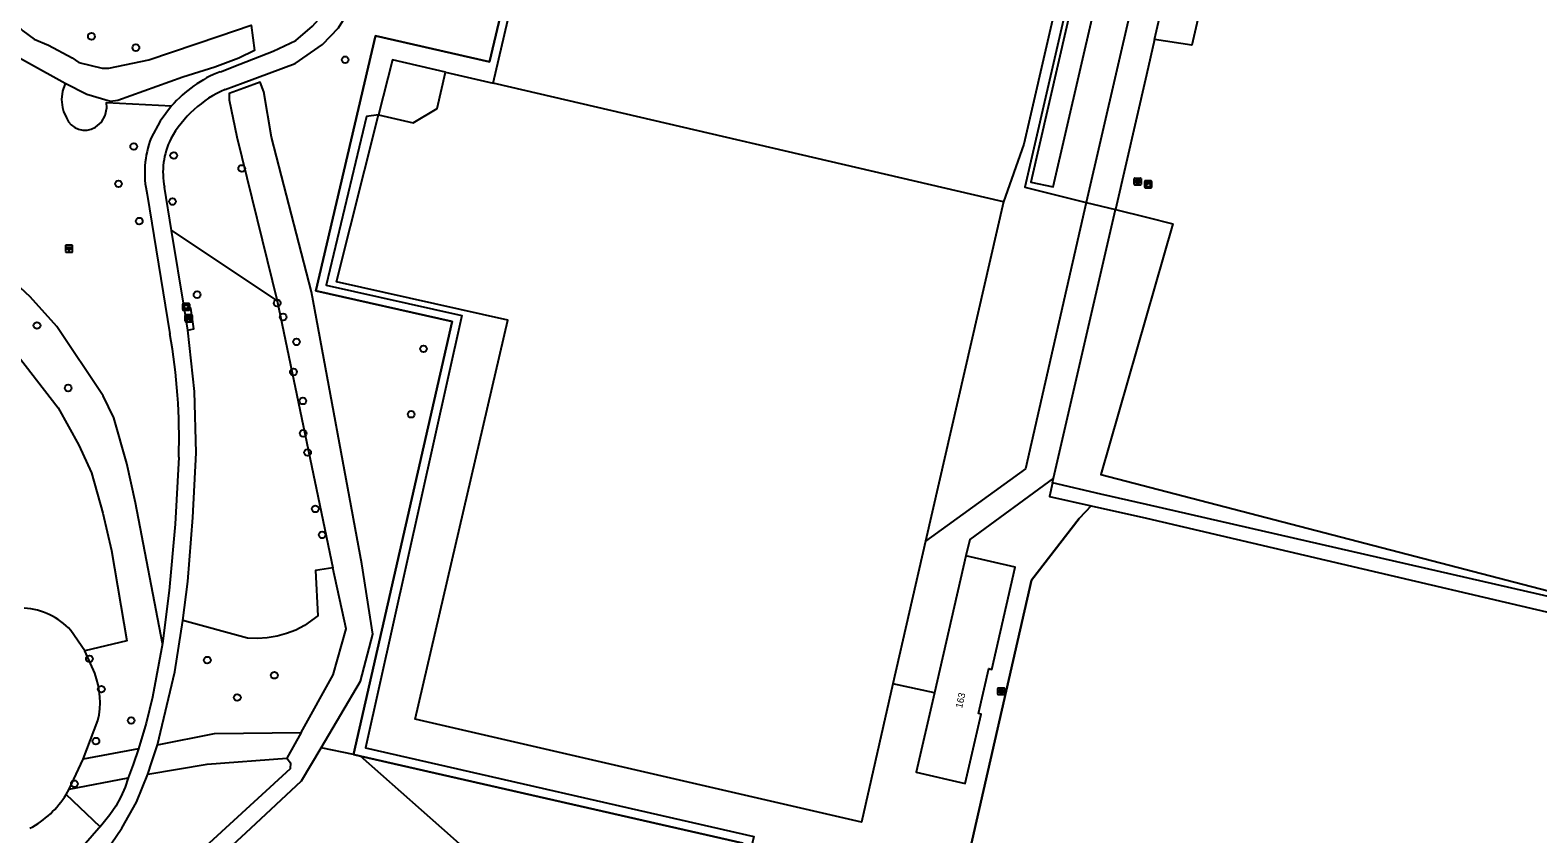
# Model space of a CAD drawing. Extents: x 160203 to 161526, y 379529 to 381797.
# Drawn here: x 160838.5 to 161056.6, y 381499.2 to 381615.5 of the extents above; entities that cross this region are included whole.
import ezdxf

# ---------------------------------------------------------------- set-up
doc = ezdxf.new("R2010")
doc.units = 0
for name, color, linetype in [('IMGEO_Afvalbak', 7, 'Continuous'), ('IMGEO_Bank', 7, 'Continuous'), ('IMGEO_Boom', 7, 'Continuous'), ('IMGEO_Erf', 7, 'Continuous'), ('IMGEO_Fietspad_gesloten', 7, 'Continuous'), ('IMGEO_Gemengd_bos', 7, 'Continuous'), ('IMGEO_Grasland_agrarisch', 7, 'Continuous'), ('IMGEO_Grasland_overig', 7, 'Continuous'), ('IMGEO_Groenvoorziening', 7, 'Continuous'), ('IMGEO_Hectometerpaal', 7, 'Continuous'), ('IMGEO_Hek', 7, 'Continuous'), ('IMGEO_Kast', 7, 'Continuous'), ('IMGEO_Loofbos', 7, 'Continuous'), ('IMGEO_Meer_plas_ven_vijver', 7, 'Continuous'), ('IMGEO_Pand', 7, 'Continuous'), ('IMGEO_Pand_nummerreeks', 7, 'Continuous'), ('IMGEO_Rijbaan_lokaal_gesloten', 7, 'Continuous'), ('IMGEO_Rioolput', 7, 'Continuous'), ('IMGEO_Voetpad_gesloten', 7, 'Continuous'), ('IMGEO_Voetpad_open', 7, 'Continuous'), ('IMGEO_Waterloop', 7, 'Continuous')]:
    doc.layers.add(name, color=color, linetype=linetype)

msp = doc.modelspace()

# ---------------------------------------------------------------- linework, layer by layer
at = {"layer": 'IMGEO_Afvalbak'}
for p, q in [((160860.57, 381575.04), (160860.57, 381575.84)), ((160860.57, 381575.84), (160860.57, 381575.04)), ((160860.67, 381575.94), (160861.45, 381575.94)), ((160861.45, 381575.94), (160860.67, 381575.94)), ((160861.45, 381574.94), (160860.67, 381574.94)), ((160860.67, 381574.94), (160861.45, 381574.94)), ((160861.55, 381575.84), (160861.55, 381575.04)), ((160861.55, 381575.04), (160861.55, 381575.84))]:
    msp.add_line(p, q, dxfattribs=at)
msp.add_lwpolyline([(160860.71, 381575.66), (160861.41, 381575.66), (160861.26, 381575.19), (160860.86, 381575.19), (160860.71, 381575.66)], dxfattribs=at)
for centre, start, end in [((160860.67, 381575.84), 90, 180), ((160860.67, 381575.84), 90, 180), ((160860.67, 381575.04), 180, 270), ((160860.67, 381575.04), 180, 270), ((160861.45, 381575.84), 0, 90), ((160861.45, 381575.84), 360, 90), ((160861.45, 381575.04), 270, 0), ((160861.45, 381575.04), 270, 0)]:
    msp.add_arc(centre, 0.1, start, end, dxfattribs=at)
at = {"layer": 'IMGEO_Bank'}
for p, q in [((160860.92, 381573.34), (160860.92, 381574.18)), ((160860.92, 381574.18), (160860.92, 381573.34)), ((160861, 381574.26), (160861.84, 381574.26)), ((160861.84, 381574.26), (160861, 381574.26)), ((160861.92, 381574.19), (160861.92, 381573.35)), ((160861.92, 381573.35), (160861.92, 381574.19)), ((160861.85, 381573.26), (160861.01, 381573.26)), ((160861.01, 381573.26), (160861.85, 381573.26)), ((160861.23, 381573.77), (160861.23, 381573.87)), ((160861.62, 381573.66), (160861.23, 381573.66)), ((160861.56, 381573.88), (160861.28, 381573.88)), ((160861.28, 381573.87), (160861.28, 381573.77)), ((160861.28, 381573.76), (160861.56, 381573.76)), ((160861.57, 381573.77), (160861.57, 381573.87)), ((160861.61, 381573.87), (160861.61, 381573.77))]:
    msp.add_line(p, q, dxfattribs=at)
for points in [[(160861.17, 381573.66), (160861.03, 381573.66), (160861.14, 381573.76), (160861.23, 381573.76)], [(160861.23, 381573.88), (160861.14, 381573.88), (160861.14, 381574.04), (160861.7, 381574.04), (160861.7, 381573.88), (160861.62, 381573.88)], [(160861.22, 381573.65), (160861.22, 381573.45), (160861.18, 381573.45), (160861.18, 381573.65)], [(160861.62, 381573.76), (160861.7, 381573.76), (160861.82, 381573.66), (160861.68, 381573.66)], [(160861.67, 381573.65), (160861.67, 381573.45), (160861.63, 381573.45), (160861.63, 381573.65)]]:
    msp.add_lwpolyline(points, dxfattribs=at)
for centre, radius, start, end in [((160861, 381574.18), 0.0779, 92.4484, 184.2845), ((160861, 381574.18), 0.0779, 92.4484, 184.2845), ((160861.85, 381574.18), 0.0779, 2.4484, 94.2845), ((160861.85, 381574.18), 0.0779, 2.4484, 94.2845), ((160861, 381573.34), 0.0779, 182.4484, 274.2845), ((160861, 381573.34), 0.0779, 182.4484, 274.2845), ((160861.17, 381573.65), 0.00671, 2.8957, 87.1043), ((160861.23, 381573.65), 0.00671, 92.8957, 177.1043), ((160861.23, 381573.87), 0.00671, 2.8957, 87.1043), ((160861.23, 381573.77), 0.00671, 272.8957, 357.1043), ((160861.28, 381573.87), 0.00671, 92.8957, 177.1043), ((160861.28, 381573.77), 0.00671, 182.8957, 267.1043), ((160861.56, 381573.87), 0.00671, 2.8957, 87.1043), ((160861.56, 381573.77), 0.00671, 272.8957, 357.1043), ((160861.62, 381573.87), 0.00671, 92.8957, 177.1043), ((160861.62, 381573.77), 0.00671, 182.8957, 267.1043), ((160861.62, 381573.65), 0.00671, 2.8957, 87.1043), ((160861.68, 381573.65), 0.00671, 92.8957, 177.1043), ((160861.85, 381573.34), 0.0779, 272.4484, 4.2845), ((160861.85, 381573.34), 0.0779, 272.4484, 4.2845)]:
    msp.add_arc(centre, radius, start, end, dxfattribs=at)
at = {"layer": 'IMGEO_Boom'}
for centre in [(160847.35, 381614.57), (160853.79, 381612.93), (160884.06, 381611.18), (160853.48, 381598.63), (160859.26, 381597.33), (160869.1, 381595.46), (160851.27, 381593.23), (160859.09, 381590.66), (160854.28, 381587.84), (160862.64, 381577.19), (160874.24, 381575.99), (160875.1, 381573.96), (160839.48, 381572.73), (160877.02, 381570.36), (160895.4, 381569.36), (160876.58, 381566.01), (160843.99, 381563.69), (160877.95, 381561.82), (160893.61, 381559.89), (160877.99, 381557.14), (160878.63, 381554.36), (160879.75, 381546.2), (160880.74, 381542.44), (160847.06, 381524.51), (160864.12, 381524.33), (160873.82, 381522.13), (160848.79, 381520.12), (160868.46, 381518.92), (160853.1, 381515.59), (160848.01, 381512.61), (160844.89, 381506.44)]:
    msp.add_circle(centre, 0.489, dxfattribs=at)
at = {"layer": 'IMGEO_Erf'}
msp.add_lwpolyline([(160995.51, 381589.5), (161000, 381588.39), (161003.8, 381587.42), (160993.42, 381551.2), (161084.45, 381527.5)], dxfattribs=at)
at = {"layer": 'IMGEO_Fietspad_gesloten'}
for points in [[(160866.01, 381609.45), (160868.82, 381610.55), (160873.65, 381612.43), (160876.94, 381613.98), (160879.32, 381616.02), (160881.4, 381618.35), (160882.64, 381620.41)], [(160866.7, 381606.9), (160869.29, 381607.86), (160876.81, 381610.66), (160880.8, 381613.41), (160883.08, 381615.78), (160885.06, 381618.97)], [(160858.95, 381604.5), (160857.3, 381602.31), (160855.99, 381599.9)], [(160855.41, 381591.69), (160858.71, 381571.54)], [(160858.94, 381586.5), (160857.92, 381592.75)], [(160860.81, 381575.09), (160858.94, 381586.5)], [(160861.31, 381572.06), (160860.81, 381575.09)], [(160860.58, 381530.07), (160861.29, 381535.68), (160862.05, 381544.98), (160862.52, 381554.3), (160862.26, 381563.2), (160861.31, 381572.06)], [(160859.99, 381553.67), (160859.49, 381544.01), (160858.58, 381534.38), (160857.62, 381526.74)], [(160856.92, 381512.07), (160859.4, 381522.61), (160860.58, 381530.07)], [(160857.62, 381526.74), (160856.17, 381518.97), (160855.27, 381515.21), (160854.18, 381511.5)], [(160854.18, 381511.5), (160853.38, 381509.23), (160852.69, 381507.31)], [(160855.5, 381507.81), (160856.11, 381509.63), (160856.92, 381512.07)], [(160838.96, 381485.78), (160838.99, 381485.85), (160839.03, 381485.91), (160840.34, 381487.3), (160850.2, 381497.74), (160851.76, 381500), (160853.86, 381503.79), (160855.5, 381507.81)], [(160852.69, 381507.31), (160852.23, 381505.95), (160851.61, 381504.54), (160850.88, 381503.2), (160850.02, 381501.93), (160849.06, 381500.74), (160848.6, 381500.19)], [(160848.6, 381500.19), (160848.43, 381500), (160844.57, 381495.58), (160840.56, 381491.31), (160838.08, 381489.08)]]:
    msp.add_lwpolyline(points, dxfattribs=at)
for centre, radius, start, end in [((160872.64, 381592.48), 18.23, 111.3553, 138.7094), ((160873.48, 381591.55), 16.78, 113.8365, 150.8354), ((160869.23, 381594.83), 14.17, 159.024, 192.782), ((160868.65, 381594.9), 10.94, 153.8348, 191.3557), ((160772.88, 381556.45), 87.15, 358.1761, 9.9705)]:
    msp.add_arc(centre, radius, start, end, dxfattribs=at)
at = {"layer": 'IMGEO_Gemengd_bos'}
for points in [[(160857.62, 381526.74), (160853.72, 381547.09), (160852.49, 381552.77), (160850.58, 381559.39), (160849.05, 381562.56), (160842.35, 381572.57), (160838.48, 381576.89), (160833.45, 381581.58), (160815.55, 381601.54)], [(160786.68, 381569.18), (160790.59, 381565.54), (160791.53, 381566.74), (160816.94, 381591.26), (160835.81, 381569.57), (160842.52, 381560.84), (160845.54, 381555.42), (160847.35, 381551.42), (160849.01, 381545.59), (160850.25, 381540.18), (160852.46, 381527.1), (160846.42, 381525.68)], [(160848.6, 381500.19), (160843.7, 381504.9)]]:
    msp.add_lwpolyline(points, dxfattribs=at)
at = {"layer": 'IMGEO_Grasland_agrarisch'}
msp.add_lwpolyline([(160992.01, 381546.65), (161000, 381544.86), (161087.73, 381524.31), (161123.21, 381516.23), (161094.22, 381388.52), (161000, 381410.48), (160979.1, 381415.39)], dxfattribs=at)
at = {"layer": 'IMGEO_Grasland_overig'}
for points in [[(160888.89, 381603.21), (160893.92, 381602.07), (160897.36, 381604.11), (160898.56, 381609.4)], [(160898.56, 381609.4), (160905.47, 381607.79)], [(160979.33, 381590.62), (160905.47, 381607.79)], [(160888.89, 381603.21), (160887.17, 381602.96), (160881.34, 381578.59), (160900.93, 381574.16), (160887, 381511.65), (160943.21, 381498.82), (160926.61, 381427.71), (160950.89, 381422.03), (160966.02, 381487.2), (160966.83, 381487.02)], [(160963.3, 381520.89), (160958.75, 381500.88), (160894.19, 381515.8), (160907.61, 381573.5), (160882.79, 381579.07), (160888.89, 381603.21)], [(160979.33, 381590.62), (160968.05, 381541.52)], [(160986.4, 381549.95), (160986.57, 381550.67)], [(160986.4, 381549.95), (160985.95, 381548.01), (160992.01, 381546.65)], [(160992.01, 381546.65), (160990.26, 381544.79), (160983.38, 381535.9), (160973.76, 381493.85), (160972.12, 381488.02)]]:
    msp.add_lwpolyline(points, dxfattribs=at)
at = {"layer": 'IMGEO_Groenvoorziening'}
for points in [[(160905.47, 381607.79), (160932.99, 381725.88), (161007.56, 381708.83), (160982.28, 381598.99), (160979.33, 381590.62)], [(161031.06, 381706.3), (161030.96, 381705.4), (161029.69, 381694.26), (161028.46, 381694.55), (161025.49, 381695.25), (161006.56, 381613.31), (161001.18, 381614.12)], [(160898.56, 381609.4), (160890.91, 381611.18), (160888.89, 381603.21)], [(161084.45, 381527.5), (161000, 381546.84), (160993.38, 381548.35), (160986.4, 381549.95)], [(160886.3, 381510.43), (160885.25, 381510.67)]]:
    msp.add_lwpolyline(points, dxfattribs=at)
at = {"layer": 'IMGEO_Hectometerpaal'}
for p, q in [((160843.62, 381584.26), (160843.62, 381583.42)), ((160843.62, 381584.26), (160843.62, 381583.42)), ((160844.53, 381584.35), (160843.69, 381584.35)), ((160844.53, 381584.35), (160843.69, 381584.35)), ((160843.7, 381583.35), (160844.54, 381583.35)), ((160843.7, 381583.35), (160844.54, 381583.35)), ((160844.62, 381583.43), (160844.62, 381584.27)), ((160844.62, 381583.43), (160844.62, 381584.27))]:
    msp.add_line(p, q, dxfattribs=at)
msp.add_lwpolyline([(160844.14, 381583.49), (160844.08, 381583.49), (160844.08, 381583.79), (160843.86, 381583.79), (160843.86, 381584.06), (160844.36, 381584.06), (160844.36, 381583.79), (160844.14, 381583.79), (160844.14, 381583.49)], dxfattribs=at)
for centre, start, end in [((160843.69, 381584.27), 92.4484, 184.2845), ((160843.69, 381584.27), 92.4484, 184.2845), ((160843.69, 381583.42), 182.4484, 274.2845), ((160843.69, 381583.42), 182.4484, 274.2845), ((160844.54, 381584.27), 2.4484, 94.2845), ((160844.54, 381584.27), 2.4484, 94.2845), ((160844.54, 381583.42), 272.4484, 4.2845), ((160844.54, 381583.42), 272.4484, 4.2845)]:
    msp.add_arc(centre, 0.0779, start, end, dxfattribs=at)
at = {"layer": 'IMGEO_Hek'}
for points in [[(160931.91, 381727.39), (160911.88, 381640.18), (160904.95, 381610.88), (160888.45, 381614.64), (160879.8, 381577.74), (160899.54, 381573.29), (160885.25, 381510.67)], [(161000, 381669.16), (160982.41, 381592.73), (160991.3, 381590.54)], [(160973.76, 381493.85), (160983.38, 381535.9), (160990.26, 381544.79)], [(160885.25, 381510.67), (160886.3, 381510.43)], [(160886.3, 381510.43), (160932.03, 381500)], [(160932.03, 381500), (160941.58, 381497.82), (160925.05, 381426.94)]]:
    msp.add_lwpolyline(points, dxfattribs=at)
at = {"layer": 'IMGEO_Kast'}
for p, q in [((160999.74, 381592.73), (160999.74, 381593.57)), ((160999.74, 381593.57), (160999.74, 381592.73)), ((160999.81, 381593.66), (161000.65, 381593.66)), ((161000.65, 381593.66), (160999.81, 381593.66)), ((161000.66, 381592.66), (160999.82, 381592.66)), ((160999.82, 381592.66), (161000.66, 381592.66)), ((161000.74, 381593.58), (161000.74, 381592.74)), ((161000.74, 381592.74), (161000.74, 381593.58))]:
    msp.add_line(p, q, dxfattribs=at)
for points in [[(160999.93, 381593.45), (161000.53, 381593.45), (161000.53, 381593.36), (160999.93, 381593.36), (160999.93, 381593.45)], [(160999.93, 381593.27), (161000.53, 381593.27), (161000.53, 381592.78), (160999.93, 381592.78), (160999.93, 381593.27)]]:
    msp.add_lwpolyline(points, dxfattribs=at)
msp.add_circle((161000.02, 381593.12), 0.0377, dxfattribs=at)
for centre, start, end in [((160999.82, 381593.58), 92.4484, 184.2845), ((160999.82, 381593.58), 92.4484, 184.2845), ((160999.82, 381592.74), 182.4484, 274.2845), ((160999.82, 381592.74), 182.4484, 274.2845), ((161000.66, 381593.58), 2.4484, 94.2845), ((161000.66, 381593.58), 2.4484, 94.2845), ((161000.66, 381592.74), 272.4484, 4.2845), ((161000.66, 381592.74), 272.4484, 4.2845)]:
    msp.add_arc(centre, 0.0779, start, end, dxfattribs=at)
at = {"layer": 'IMGEO_Loofbos'}
for points in [[(160885.25, 381510.67), (160899.54, 381573.29), (160879.8, 381577.74), (160888.45, 381614.64), (160904.95, 381610.88), (160911.88, 381640.18), (160931.91, 381727.39), (161000, 381711.85), (161009.35, 381709.72)], [(161009.35, 381709.72), (161000, 381669.16), (160982.41, 381592.73), (160991.3, 381590.54)], [(160843.54, 381607.74), (160843.18, 381606.62), (160843.05, 381605.45), (160843.17, 381604.28), (160843.32, 381603.71), (160843.73, 381602.76), (160844.03, 381602.22), (160844.44, 381601.76), (160844.94, 381601.4), (160845.5, 381601.14), (160846.1, 381601.01), (160846.72, 381601.01), (160847.32, 381601.13), (160847.95, 381601.41), (160848.79, 381602.16), (160849.35, 381603.14), (160849.58, 381604.23), (160849.54, 381605.01), (160858.95, 381604.5)], [(160858.94, 381586.5), (160874.25, 381576.3)], [(160882.27, 381537.67), (160879.77, 381537.28), (160880.11, 381530.71), (160878.2, 381529.35), (160876.93, 381528.68), (160875.59, 381528.16), (160874.21, 381527.77), (160872.79, 381527.53), (160871.36, 381527.44), (160869.92, 381527.49), (160860.58, 381530.07)], [(160885.25, 381510.67), (160880.59, 381511.61)], [(160905.25, 381439), (160909.01, 381442.44), (160930.91, 381454.72), (160925.97, 381475.24), (160898.06, 381500), (160886.3, 381510.43)], [(160925.05, 381426.94), (160941.58, 381497.82), (160932.03, 381500), (160886.3, 381510.43)]]:
    msp.add_lwpolyline(points, dxfattribs=at)
at = {"layer": 'IMGEO_Meer_plas_ven_vijver'}
for points in [[(160846.42, 381525.68), (160844.37, 381528.62)], [(160847.83, 381522.43), (160846.42, 381525.68)], [(160846.18, 381509.99), (160848.3, 381515.57)], [(160843.7, 381504.9), (160844.12, 381505.65)]]:
    msp.add_lwpolyline(points, dxfattribs=at)
for centre, radius, start, end in [((160837.07, 381521.95), 9.89, 42.4584, 86.7095), ((160836.78, 381518.23), 11.82, 346.9738, 20.7973), ((160832.39, 381511.75), 13.22, 297.3162, 328.7986)]:
    msp.add_arc(centre, radius, start, end, dxfattribs=at)
at = {"layer": 'IMGEO_Pand'}
for points in [[(160969.31, 381519.57), (160966.66, 381508.09), (160973.78, 381506.45), (160976.1, 381516.5), (160975.69, 381516.6), (160977.18, 381523.09), (160977.61, 381522.99), (160981.01, 381537.77), (160973.89, 381539.41)], [(160973.89, 381539.41), (160969.31, 381519.57)]]:
    msp.add_lwpolyline(points, dxfattribs=at)
at = {"layer": 'IMGEO_Rijbaan_lokaal_gesloten'}
for points in [[(161018.41, 381708.29), (161000, 381628.33), (160991.3, 381590.54)], [(161001.18, 381614.12), (161022.69, 381707.62)], [(161001.18, 381614.12), (161000, 381608.98), (160995.51, 381589.5)], [(160991.3, 381590.54), (160995.51, 381589.5)]]:
    msp.add_lwpolyline(points, dxfattribs=at)
at = {"layer": 'IMGEO_Rioolput'}
for p, q in [((160998.22, 381593.13), (160998.22, 381593.98)), ((160998.29, 381594.06), (160999.15, 381594.06)), ((160998.71, 381593.84), (160998.73, 381593.84)), ((160999.22, 381593.98), (160999.22, 381593.13)), ((160999.15, 381593.06), (160998.29, 381593.06)), ((160998.73, 381593.28), (160998.71, 381593.28)), ((160978.48, 381519.38), (160978.48, 381520.24)), ((160978.55, 381520.31), (160979.41, 381520.31)), ((160978.97, 381520.09), (160978.99, 381520.09)), ((160979.48, 381520.24), (160979.48, 381519.38)), ((160979.41, 381519.31), (160978.55, 381519.31)), ((160978.99, 381519.53), (160978.96, 381519.53))]:
    msp.add_line(p, q, dxfattribs=at)
for points in [[(160998.22, 381593.13), (160998.22, 381593.98)], [(160998.29, 381594.06), (160999.15, 381594.06)], [(160998.81, 381593.75), (160998.56, 381593.76), (160998.56, 381593.36)], [(160999.22, 381593.98), (160999.22, 381593.13)], [(160999.15, 381593.06), (160998.29, 381593.06)], [(160998.56, 381593.36), (160998.68, 381593.36), (160998.68, 381593.52), (160998.69, 381593.52)], [(160998.74, 381593.68), (160998.68, 381593.68), (160998.68, 381593.59)], [(160998.68, 381593.59), (160998.73, 381593.59)], [(160998.74, 381593.49), (160998.81, 381593.36), (160998.95, 381593.36), (160998.88, 381593.48)], [(160978.48, 381519.38), (160978.48, 381520.24)], [(160978.55, 381520.31), (160979.41, 381520.31)], [(160979.07, 381520.01), (160978.82, 381520.01), (160978.82, 381519.61)], [(160978.82, 381519.61), (160978.94, 381519.61), (160978.94, 381519.77), (160978.95, 381519.77)], [(160978.99, 381519.93), (160978.94, 381519.93), (160978.94, 381519.85)], [(160978.94, 381519.85), (160978.99, 381519.85)], [(160979, 381519.74), (160979.07, 381519.61), (160979.21, 381519.61), (160979.14, 381519.74)], [(160979.48, 381520.24), (160979.48, 381519.38)], [(160979.41, 381519.31), (160978.55, 381519.31)]]:
    msp.add_lwpolyline(points, dxfattribs=at)
for centre, radius, start, end in [((160998.3, 381593.98), 0.0765, 91.552, 178.448), ((160998.3, 381593.98), 0.0765, 91.552, 178.448), ((160998.81, 381593.64), 0.109, 350.3612, 89.416), ((160999.14, 381593.98), 0.0765, 1.552, 88.448), ((160999.14, 381593.98), 0.0765, 1.552, 88.448), ((160998.3, 381593.13), 0.0765, 181.552, 268.448), ((160998.3, 381593.13), 0.0765, 181.552, 268.448), ((160998.69, 381593.47), 0.0533, 26.0293, 88.6989), ((160998.72, 381593.78), 0.19, 274.7715, 282.9687), ((160998.74, 381593.58), 0.0964, 77.0061, 93.1865), ((160998.76, 381593.64), 0.0378, 276.6634, 79.6772), ((160998.81, 381593.64), 0.112, 277.5842, 350.9817), ((160998.79, 381593.43), 0.108, 29.5134, 73.7905), ((160999.14, 381593.13), 0.0765, 271.552, 358.448), ((160999.14, 381593.13), 0.0765, 271.552, 358.448), ((160978.56, 381520.23), 0.0765, 91.552, 178.448), ((160978.56, 381520.23), 0.0765, 91.552, 178.448), ((160978.95, 381519.72), 0.0533, 26.0293, 88.6989), ((160979, 381519.83), 0.0964, 77.0061, 93.1865), ((160978.98, 381520.04), 0.19, 274.7715, 282.9687), ((160979.01, 381519.89), 0.0378, 276.6634, 79.6772), ((160979.07, 381519.9), 0.109, 350.3612, 89.416), ((160979.07, 381519.9), 0.112, 277.5842, 350.9817), ((160979.05, 381519.68), 0.108, 29.5134, 73.7905), ((160979.4, 381520.23), 0.0765, 1.552, 88.448), ((160979.4, 381520.23), 0.0765, 1.552, 88.448), ((160978.56, 381519.38), 0.0765, 181.552, 268.448), ((160978.56, 381519.38), 0.0765, 181.552, 268.448), ((160979.4, 381519.38), 0.0765, 271.552, 358.448), ((160979.4, 381519.38), 0.0765, 271.552, 358.448)]:
    msp.add_arc(centre, radius, start, end, dxfattribs=at)
for centre, major_axis, ratio, start_param, end_param in [((160998.71, 381593.56), (-0.387, 0.002), 0.722429, 4.712389, 7.853982), ((160998.73, 381593.56), (-0.39, 0.002), 0.717154, 1.570796, 4.712389), ((160978.97, 381519.81), (-0.387, 0.002), 0.722429, 4.712389, 7.853982), ((160978.99, 381519.81), (-0.39, 0.002), 0.717154, 1.570796, 4.712389)]:
    msp.add_ellipse(centre, major_axis=major_axis, ratio=ratio, start_param=start_param, end_param=end_param, dxfattribs=at)
at = {"layer": 'IMGEO_Voetpad_gesloten'}
for points in [[(160991.3, 381590.54), (160982.5, 381552.01), (160968.05, 381541.52)], [(160986.57, 381550.67), (160995.51, 381589.5)], [(160986.57, 381550.67), (160974.43, 381541.76), (160973.89, 381539.41)], [(160968.05, 381541.52), (160963.3, 381520.89)], [(160969.31, 381519.57), (160963.3, 381520.89)]]:
    msp.add_lwpolyline(points, dxfattribs=at)
at = {"layer": 'IMGEO_Voetpad_open'}
msp.add_lwpolyline([(160861.31, 381572.06), (160862.18, 381572.26), (160861.74, 381575.22), (160860.81, 381575.09)], dxfattribs=at)
at = {"layer": 'IMGEO_Waterloop'}
for points in [[(161009.85, 381709.64), (161009.91, 381709.33), (161000, 381666.23), (160983.27, 381593.49), (160986.49, 381592.82), (161000, 381651.24), (161013.36, 381708.99), (161013.36, 381709.08)], [(160834.81, 381618), (160837.43, 381615.39), (160839.09, 381614.16), (160841.13, 381613.3), (160844.57, 381611.46), (160845.51, 381610.79), (160848.89, 381609.97), (160849.87, 381609.97), (160855.66, 381611.15), (160865.78, 381614.6), (160870.45, 381616.2), (160870.94, 381612.5), (160868.68, 381611.41), (160865.19, 381610.1), (160860.57, 381608.68), (160851.16, 381605.3), (160850.11, 381605.16), (160846.71, 381606.14), (160843.54, 381607.74)], [(160843.54, 381607.74), (160832.47, 381613.87), (160831.45, 381614.31)], [(160880.59, 381511.61), (160886.3, 381521.28), (160888.09, 381528.06), (160886.5, 381538.24), (160879.21, 381577.63), (160873.43, 381599.98), (160872.3, 381606.55), (160871.76, 381607.92), (160869.42, 381607.08), (160867.29, 381606.31), (160867.27, 381605.39), (160868.41, 381600.01), (160874.25, 381576.3)], [(160874.25, 381576.3), (160882.27, 381537.67)], [(160877.7, 381513.84), (160882.31, 381522.21), (160884.23, 381528.87), (160882.27, 381537.67)], [(160856.92, 381512.07), (160865.15, 381513.7), (160877.7, 381513.84)], [(160877.7, 381513.84), (160875.64, 381510.14)], [(160854.18, 381511.5), (160846.18, 381509.99)], [(160849.02, 381474.36), (160852.47, 381475.69), (160853.37, 381477.79), (160857.89, 381488.39), (160870.4, 381500), (160877.77, 381506.85), (160880.59, 381511.61)], [(160844.12, 381505.65), (160846.18, 381509.99)], [(160875.64, 381510.14), (160876.18, 381509.46), (160876.09, 381508.6), (160866.74, 381500), (160855.41, 381489.58), (160847.38, 381482.56)], [(160855.5, 381507.81), (160864.11, 381509.29), (160875.64, 381510.14)], [(160844.12, 381505.65), (160852.69, 381507.31)]]:
    msp.add_lwpolyline(points, dxfattribs=at)

# ---------------------------------------------------------------- texts
at = {"layer": 'IMGEO_Pand_nummerreeks'}
msp.add_text('163', height=1, rotation=76.8213, dxfattribs=at).set_placement((160973.32, 381517.3))

doc.saveas('drawing.dxf')
